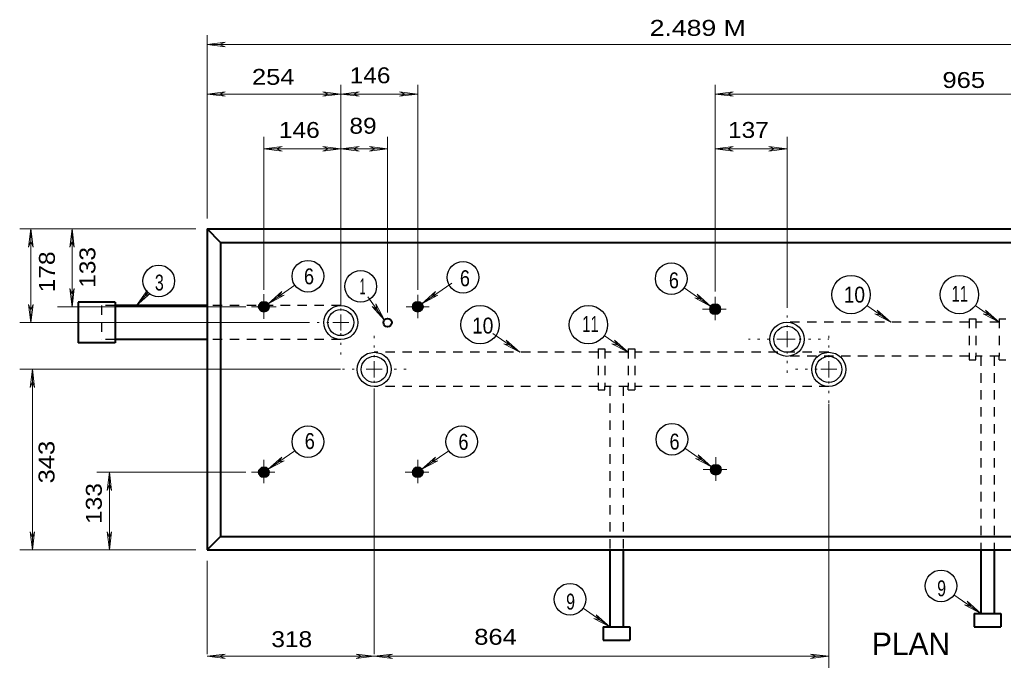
# Model space of a CAD drawing. Extents: x 312583 to 312854, y 144419 to 144597.
# Drawn here: x 312769.06 to 312816.07, y 144549.21 to 144579.91 of the extents above; entities that cross this region are included whole.
import ezdxf
from ezdxf.enums import TextEntityAlignment as Align

# ---------------------------------------------------------------- set-up
doc = ezdxf.new("R2010")
doc.units = 0
doc.header["$LTSCALE"] = 0.3
doc.linetypes.add('DOTTED', pattern=[1.5, 0.3, -1.2])
doc.linetypes.add('SHORT_DASHED', pattern=[2.7, 1.5, -1.2])
doc.layers.add('1', color=7, linetype='Continuous', lineweight=25)
doc.layers.add('2', color=7, linetype='Continuous', lineweight=13)

msp = doc.modelspace()

# ---------------------------------------------------------------- linework, layer by layer
at = {"layer": '1', "lineweight": 40}
for p, q in [((312778.0166, 144569.9153), (312840.6303, 144569.9153)), ((312778.0166, 144569.9153), (312778.0166, 144554.5819)), ((312778.6606, 144569.2713), (312778.0166, 144569.9153)), ((312778.6606, 144569.2713), (312839.994, 144569.2713)), ((312778.6606, 144569.2713), (312778.6606, 144555.2183)), ((312773.616, 144566.4116), (312771.8526, 144566.4116)), ((312771.8526, 144566.4116), (312771.8526, 144564.4643)), ((312773.616, 144566.4116), (312773.616, 144564.4643)), ((312778.0166, 144566.2583), (312773.616, 144566.2583)), ((312778.0166, 144564.6253), (312773.616, 144564.6253)), ((312773.616, 144564.4643), (312771.8526, 144564.4643)), ((312778.0166, 144554.5819), (312778.6606, 144555.2183)), ((312778.6606, 144555.2183), (312839.994, 144555.2183)), ((312778.0166, 144554.5819), (312840.6303, 144554.5819)), ((312797.2676, 144554.5819), (312797.2676, 144550.9019)), ((312797.904, 144554.5819), (312797.904, 144550.9019)), ((312814.993, 144554.5819), (312814.993, 144551.5459)), ((312815.637, 144554.5819), (312815.637, 144551.5459)), ((312814.6786, 144551.5459), (312815.9513, 144551.5459)), ((312814.6786, 144551.5459), (312814.6786, 144550.9019)), ((312815.9513, 144551.5459), (312815.9513, 144550.9019)), ((312796.9456, 144550.9019), (312798.226, 144550.9019)), ((312796.9456, 144550.9019), (312796.9456, 144550.2656)), ((312798.226, 144550.9019), (312798.226, 144550.2656)), ((312814.6786, 144550.9019), (312815.9513, 144550.9019)), ((312796.9456, 144550.2656), (312798.226, 144550.2656))]:
    msp.add_line(p, q, dxfattribs=at)
at = {"layer": '1', "linetype": 'SHORT_DASHED'}
for p, q in [((312772.972, 144566.2583), (312772.972, 144564.6253)), ((312773.616, 144566.2583), (312772.972, 144566.2583)), ((312784.4106, 144566.2583), (312778.0166, 144566.2583)), ((312814.4333, 144565.4533), (312805.7316, 144565.4533)), ((312814.4333, 144565.6143), (312814.4333, 144563.6669)), ((312814.4333, 144565.6143), (312814.7553, 144565.6143)), ((312814.7553, 144565.6143), (312814.7553, 144563.8279)), ((312815.8746, 144565.4533), (312814.7553, 144565.4533)), ((312815.8746, 144565.6143), (312815.8746, 144563.8279)), ((312815.8746, 144565.6143), (312816.189, 144565.6143)), ((312773.616, 144564.6253), (312772.972, 144564.6253)), ((312784.4106, 144564.6253), (312778.0166, 144564.6253)), ((312796.708, 144564.0196), (312786.0053, 144564.0196)), ((312796.708, 144564.1806), (312796.708, 144562.2333)), ((312796.708, 144564.1806), (312797.0223, 144564.1806)), ((312797.0223, 144564.1806), (312797.0223, 144562.3866)), ((312798.1416, 144564.0196), (312797.0223, 144564.0196)), ((312798.1416, 144564.1806), (312798.1416, 144562.3866)), ((312798.1416, 144564.1806), (312798.4636, 144564.1806)), ((312798.4636, 144564.1806), (312798.4636, 144562.2333)), ((312807.725, 144564.0196), (312798.4636, 144564.0196)), ((312814.4333, 144563.8279), (312805.7316, 144563.8279)), ((312814.4333, 144563.6669), (312814.7553, 144563.6669)), ((312814.7553, 144563.6669), (312814.7553, 144563.8279)), ((312815.8746, 144563.8279), (312814.7553, 144563.8279)), ((312814.993, 144563.8279), (312814.993, 144554.5819)), ((312815.637, 144563.8279), (312815.637, 144554.5819)), ((312815.8746, 144563.6669), (312815.8746, 144563.8279)), ((312815.8746, 144563.6669), (312816.189, 144563.6669)), ((312796.708, 144562.3866), (312786.0053, 144562.3866)), ((312796.708, 144562.2333), (312797.0223, 144562.2333)), ((312797.0223, 144562.2333), (312797.0223, 144562.3866)), ((312798.1416, 144562.3866), (312797.0223, 144562.3866)), ((312797.2676, 144562.3866), (312797.2676, 144554.5819)), ((312797.904, 144562.3866), (312797.904, 144554.5819)), ((312798.1416, 144562.2333), (312798.1416, 144562.3866)), ((312798.1416, 144562.2333), (312798.4636, 144562.2333)), ((312807.725, 144562.3866), (312798.4636, 144562.3866))]:
    msp.add_line(p, q, dxfattribs=at)
at = {"layer": '1', "lineweight": 40}
for centre, radius in [((312780.7338, 144566.1982), 0.2396), ((312780.7338, 144566.1982), 0.2156), ((312780.7338, 144566.1982), 0.1941), ((312780.7338, 144566.1982), 0.1747), ((312788.0811, 144566.1982), 0.2396), ((312788.0811, 144566.1982), 0.2156), ((312788.0811, 144566.1982), 0.1941), ((312788.0811, 144566.1982), 0.1747), ((312780.7338, 144566.1982), 0.1572), ((312780.7338, 144566.1982), 0.1415), ((312780.7338, 144566.1982), 0.1273), ((312780.7338, 144566.1982), 0.1146), ((312780.7338, 144566.1982), 0.1031), ((312780.7338, 144566.1982), 0.0928), ((312780.7338, 144566.1982), 0.0835), ((312780.7338, 144566.1982), 0.0752), ((312780.7338, 144566.1982), 0.0677), ((312780.7338, 144566.1982), 0.0609), ((312780.7338, 144566.1982), 0.0548), ((312788.0811, 144566.1982), 0.1572), ((312788.0811, 144566.1982), 0.1415), ((312788.0811, 144566.1982), 0.1273), ((312788.0811, 144566.1982), 0.1146), ((312788.0811, 144566.1982), 0.1031), ((312788.0811, 144566.1982), 0.0928), ((312788.0811, 144566.1982), 0.0835), ((312788.0811, 144566.1982), 0.0752), ((312788.0811, 144566.1982), 0.0677), ((312788.0811, 144566.1982), 0.0609), ((312788.0811, 144566.1982), 0.0548), ((312802.2963, 144566.0787), 0.2396), ((312802.2963, 144566.0787), 0.2156), ((312802.2963, 144566.0787), 0.1941), ((312802.2963, 144566.0787), 0.1747), ((312802.2963, 144566.0787), 0.1572), ((312802.2963, 144566.0787), 0.1415), ((312802.2963, 144566.0787), 0.1273), ((312802.2963, 144566.0787), 0.1146), ((312802.2963, 144566.0787), 0.1031), ((312802.2963, 144566.0787), 0.0928), ((312802.2963, 144566.0787), 0.0835), ((312802.2963, 144566.0787), 0.0752), ((312802.2963, 144566.0787), 0.0677), ((312802.2963, 144566.0787), 0.0609), ((312802.2963, 144566.0787), 0.0548), ((312786.6436, 144565.4399), 0.1996), ((312780.7338, 144558.292), 0.2396), ((312780.7338, 144558.292), 0.2156), ((312780.7338, 144558.292), 0.1941), ((312780.7338, 144558.292), 0.1747), ((312780.7338, 144558.292), 0.1572), ((312780.7338, 144558.292), 0.1415), ((312780.7338, 144558.292), 0.1273), ((312780.7338, 144558.292), 0.1146), ((312780.7338, 144558.292), 0.1031), ((312780.7338, 144558.292), 0.0928), ((312780.7338, 144558.292), 0.0835), ((312780.7338, 144558.292), 0.0752), ((312788.0811, 144558.292), 0.2396), ((312788.0811, 144558.292), 0.2156), ((312788.0811, 144558.292), 0.1941), ((312788.0811, 144558.292), 0.1747), ((312788.0811, 144558.292), 0.1572), ((312788.0811, 144558.292), 0.1415), ((312788.0811, 144558.292), 0.1273), ((312788.0811, 144558.292), 0.1146), ((312788.0811, 144558.292), 0.1031), ((312788.0811, 144558.292), 0.0928), ((312788.0811, 144558.292), 0.0835), ((312788.0811, 144558.292), 0.0752), ((312802.3283, 144558.4121), 0.2396), ((312802.3283, 144558.4121), 0.2156), ((312802.3283, 144558.4121), 0.1941), ((312802.3283, 144558.4121), 0.1747), ((312802.3283, 144558.4121), 0.1572), ((312802.3283, 144558.4121), 0.1415), ((312802.3283, 144558.4121), 0.1273), ((312802.3283, 144558.4121), 0.1146), ((312802.3283, 144558.4121), 0.1031), ((312802.3283, 144558.4121), 0.0928), ((312802.3283, 144558.4121), 0.0835), ((312802.3283, 144558.4121), 0.0752), ((312802.3283, 144558.4121), 0.0677), ((312802.3283, 144558.4121), 0.0609), ((312802.3283, 144558.4121), 0.0548), ((312780.7338, 144558.292), 0.0677), ((312780.7338, 144558.292), 0.0609), ((312780.7338, 144558.292), 0.0548), ((312788.0811, 144558.292), 0.0677), ((312788.0811, 144558.292), 0.0609), ((312788.0811, 144558.292), 0.0548)]:
    msp.add_circle(centre, radius, dxfattribs=at)
at = {"layer": '1'}
for centre, radius in [((312784.4074, 144565.4399), 0.8146), ((312784.4074, 144565.4399), 0.6232), ((312805.7304, 144564.6412), 0.8146), ((312805.7304, 144564.6412), 0.6232), ((312786.0047, 144563.2037), 0.8146), ((312807.7269, 144563.2037), 0.8146), ((312786.0047, 144563.2037), 0.6232), ((312807.7269, 144563.2037), 0.6232)]:
    msp.add_circle(centre, radius, dxfattribs=at)
at = {"layer": '2'}
for p, q in [((312778.0166, 144570.4059), (312778.0166, 144579.1689)), ((312778.0166, 144578.7243), (312778.883, 144578.8316)), ((312778.0166, 144578.7243), (312840.6303, 144578.7243)), ((312778.0166, 144578.7243), (312778.883, 144578.6169)), ((312778.883, 144578.8316), (312778.607, 144578.7243)), ((312778.883, 144578.6169), (312778.607, 144578.7243)), ((312784.4106, 144566.2276), (312784.4106, 144576.7999)), ((312788.083, 144567.0019), (312788.083, 144576.7999)), ((312802.297, 144566.9176), (312802.297, 144576.7999)), ((312778.0166, 144576.3553), (312778.883, 144576.4626)), ((312778.0166, 144576.3553), (312778.883, 144576.2479)), ((312778.883, 144576.4626), (312778.607, 144576.3553)), ((312778.883, 144576.2479), (312778.607, 144576.3553)), ((312783.5443, 144576.4626), (312783.8203, 144576.3553)), ((312784.4106, 144576.3553), (312783.5443, 144576.4626)), ((312783.5443, 144576.2479), (312783.8203, 144576.3553)), ((312784.4106, 144576.3553), (312783.5443, 144576.2479)), ((312784.4106, 144576.3553), (312785.277, 144576.4626)), ((312784.4106, 144576.3553), (312785.277, 144576.2479)), ((312785.277, 144576.4626), (312785.001, 144576.3553)), ((312785.277, 144576.2479), (312785.001, 144576.3553)), ((312787.2166, 144576.4626), (312787.4926, 144576.3553)), ((312788.083, 144576.3553), (312787.2166, 144576.4626)), ((312787.2166, 144576.4626), (312787.4926, 144576.3553)), ((312788.083, 144576.3553), (312787.2166, 144576.4626)), ((312787.2166, 144576.2479), (312787.4926, 144576.3553)), ((312788.083, 144576.3553), (312787.2166, 144576.2479)), ((312787.2166, 144576.2479), (312787.4926, 144576.3553)), ((312788.083, 144576.3553), (312787.2166, 144576.2479)), ((312802.297, 144576.3553), (312803.1633, 144576.4626)), ((312802.297, 144576.3553), (312803.1633, 144576.2479)), ((312826.5773, 144576.3553), (312802.297, 144576.3553)), ((312803.1633, 144576.4626), (312802.8873, 144576.3553)), ((312803.1633, 144576.2479), (312802.8873, 144576.3553)), ((312780.7306, 144567.0019), (312780.7306, 144574.3159)), ((312786.6416, 144565.9209), (312786.6416, 144574.3159)), ((312805.7316, 144566.2199), (312805.7316, 144574.3159)), ((312780.7306, 144573.7409), (312781.597, 144573.8483)), ((312780.7306, 144573.7409), (312781.597, 144573.6336)), ((312781.597, 144573.8483), (312781.321, 144573.7409)), ((312781.597, 144573.6336), (312781.321, 144573.7409)), ((312783.5443, 144573.8483), (312783.8203, 144573.7409)), ((312784.4106, 144573.7409), (312783.5443, 144573.8483)), ((312783.5443, 144573.6336), (312783.8203, 144573.7409)), ((312784.4106, 144573.7409), (312783.5443, 144573.6336)), ((312784.4106, 144573.7409), (312785.277, 144573.8483)), ((312784.4106, 144573.7409), (312785.277, 144573.6336)), ((312785.277, 144573.8483), (312785.001, 144573.7409)), ((312785.277, 144573.6336), (312785.001, 144573.7409)), ((312785.7753, 144573.8483), (312786.0513, 144573.7409)), ((312786.6416, 144573.7409), (312785.7753, 144573.8483)), ((312785.7753, 144573.6336), (312786.0513, 144573.7409)), ((312786.6416, 144573.7409), (312785.7753, 144573.6336)), ((312802.297, 144573.7409), (312803.1633, 144573.8483)), ((312802.297, 144573.7409), (312803.1633, 144573.6336)), ((312802.297, 144573.7409), (312805.7316, 144573.7409)), ((312803.1633, 144573.8483), (312802.8873, 144573.7409)), ((312803.1633, 144573.6336), (312802.8873, 144573.7409)), ((312804.8653, 144573.8483), (312805.1413, 144573.7409)), ((312805.7316, 144573.7409), (312804.8653, 144573.8483)), ((312804.8653, 144573.6336), (312805.1413, 144573.7409)), ((312805.7316, 144573.7409), (312804.8653, 144573.6336)), ((312777.48, 144569.9153), (312769.0593, 144569.9153)), ((312769.5916, 144569.9153), (312769.4843, 144569.0489)), ((312769.5916, 144569.9153), (312769.4843, 144569.0489)), ((312769.5916, 144565.4379), (312769.5916, 144569.9153)), ((312769.5916, 144569.9153), (312769.6989, 144569.0489)), ((312769.5916, 144569.9153), (312769.6989, 144569.0489)), ((312771.5641, 144569.9153), (312771.4568, 144569.0489)), ((312771.5641, 144566.1969), (312771.5641, 144569.9153)), ((312771.5641, 144569.9153), (312771.6714, 144569.0489)), ((312769.4843, 144569.0489), (312769.5916, 144569.3249)), ((312769.4843, 144569.0489), (312769.5916, 144569.3249)), ((312769.6989, 144569.0489), (312769.5916, 144569.3249)), ((312769.6989, 144569.0489), (312769.5916, 144569.3249)), ((312771.4568, 144569.0489), (312771.5641, 144569.3249)), ((312771.6714, 144569.0489), (312771.5641, 144569.3249)), ((312789.7083, 144567.3239), (312788.2746, 144566.3349)), ((312771.4568, 144567.0633), (312771.5641, 144566.7873)), ((312771.5641, 144566.1969), (312771.4568, 144567.0633)), ((312771.6714, 144567.0633), (312771.5641, 144566.7873)), ((312771.5641, 144566.1969), (312771.6714, 144567.0633)), ((312774.6433, 144566.2583), (312775.1493, 144566.9713)), ((312775.203, 144566.8716), (312774.6433, 144566.2583)), ((312775.1493, 144566.9713), (312775.042, 144566.6953)), ((312782.2103, 144567.2243), (312780.93, 144566.3349)), ((312780.93, 144566.3349), (312781.5816, 144566.9176)), ((312781.5816, 144566.9176), (312781.413, 144566.6723)), ((312788.2746, 144566.3349), (312788.9263, 144566.9176)), ((312788.9263, 144566.9176), (312788.7653, 144566.6723)), ((312800.8173, 144567.1016), (312802.0976, 144566.2123)), ((312774.6433, 144566.2583), (312775.3026, 144566.8256)), ((312775.3026, 144566.8256), (312775.042, 144566.6953)), ((312780.7306, 144565.6143), (312780.7306, 144566.8026)), ((312780.93, 144566.3349), (312781.7043, 144566.7413)), ((312781.7043, 144566.7413), (312781.413, 144566.6723)), ((312785.7063, 144566.6723), (312786.4883, 144565.5606)), ((312788.083, 144565.6526), (312788.083, 144566.7566)), ((312788.2746, 144566.3349), (312789.049, 144566.7413)), ((312789.049, 144566.7413), (312788.7653, 144566.6723)), ((312801.3233, 144566.6186), (312801.6146, 144566.5496)), ((312802.0976, 144566.2123), (312801.3233, 144566.6186)), ((312801.446, 144566.7949), (312801.6146, 144566.5496)), ((312802.0976, 144566.2123), (312801.446, 144566.7949)), ((312802.297, 144565.5529), (312802.297, 144566.6723)), ((312769.4843, 144566.3043), (312769.5916, 144566.0283)), ((312769.5916, 144565.4379), (312769.4843, 144566.3043)), ((312769.6989, 144566.3043), (312769.5916, 144566.0283)), ((312769.5916, 144565.4379), (312769.6989, 144566.3043)), ((312779.872, 144566.1969), (312770.8636, 144566.1969)), ((312781.321, 144566.1969), (312780.1326, 144566.1969)), ((312785.9056, 144566.2123), (312786.151, 144566.0436)), ((312786.4883, 144565.5606), (312785.9056, 144566.2123)), ((312786.0743, 144566.3349), (312786.151, 144566.0436)), ((312786.4883, 144565.5606), (312786.0743, 144566.3349)), ((312788.6273, 144566.1969), (312787.5233, 144566.1969)), ((312802.826, 144566.0819), (312801.699, 144566.0819)), ((312809.5496, 144566.2506), (312810.6996, 144565.4533)), ((312810.048, 144566.0359), (312810.209, 144565.7906)), ((312810.6996, 144565.4533), (312810.048, 144566.0359)), ((312814.7246, 144566.2506), (312815.8746, 144565.4533)), ((312815.223, 144566.0359), (312815.3916, 144565.7906)), ((312815.8746, 144565.4533), (312815.223, 144566.0359)), ((312782.839, 144565.4379), (312769.0593, 144565.4379)), ((312784.4106, 144565.4379), (312784.0273, 144565.4379)), ((312784.4106, 144565.4379), (312784.4106, 144565.8213)), ((312784.4106, 144565.4379), (312784.794, 144565.4379)), ((312784.4106, 144565.4379), (312784.4106, 144565.0546)), ((312809.9253, 144565.8596), (312810.209, 144565.7906)), ((312810.6996, 144565.4533), (312809.9253, 144565.8596)), ((312815.1003, 144565.8596), (312815.3916, 144565.7906)), ((312815.8746, 144565.4533), (312815.1003, 144565.8596)), ((312805.7316, 144564.6406), (312805.7316, 144565.0239)), ((312791.671, 144564.9166), (312792.9666, 144564.0196)), ((312792.315, 144564.6023), (312792.4836, 144564.3569)), ((312792.9666, 144564.0196), (312792.315, 144564.6023)), ((312796.9993, 144564.8169), (312798.1416, 144564.0196)), ((312797.49, 144564.6023), (312797.6586, 144564.3569)), ((312798.1416, 144564.0196), (312797.49, 144564.6023)), ((312805.7316, 144564.6406), (312805.3483, 144564.6406)), ((312805.7316, 144564.6406), (312806.115, 144564.6406)), ((312805.7316, 144564.6406), (312805.7316, 144564.2573)), ((312792.1923, 144564.4259), (312792.4836, 144564.3569)), ((312792.9666, 144564.0196), (312792.1923, 144564.4259)), ((312797.3673, 144564.4259), (312797.6586, 144564.3569)), ((312798.1416, 144564.0196), (312797.3673, 144564.4259)), ((312786.0053, 144563.2069), (312786.0053, 144563.5903)), ((312807.725, 144563.2069), (312807.725, 144563.5903)), ((312784.3876, 144563.2069), (312769.0593, 144563.2069)), ((312769.6664, 144563.2069), (312769.5591, 144562.3406)), ((312769.6664, 144563.2069), (312769.7737, 144562.3406)), ((312769.6664, 144554.5819), (312769.6664, 144563.2069)), ((312786.0053, 144563.2069), (312785.622, 144563.2069)), ((312786.0053, 144563.2069), (312786.3886, 144563.2069)), ((312786.0053, 144563.2069), (312786.0053, 144562.8236)), ((312807.725, 144563.2069), (312807.3416, 144563.2069)), ((312807.725, 144563.2069), (312808.1083, 144563.2069)), ((312807.725, 144563.2069), (312807.725, 144562.8236)), ((312769.5591, 144562.3406), (312769.6664, 144562.6166)), ((312769.7737, 144562.3406), (312769.6664, 144562.6166)), ((312786.0053, 144562.2869), (312786.0053, 144549.5986)), ((312807.725, 144561.5586), (312807.725, 144548.9546)), ((312782.2103, 144559.3199), (312780.93, 144558.4306)), ((312789.5626, 144559.3199), (312788.2746, 144558.4306)), ((312800.848, 144559.4349), (312802.1283, 144558.5456)), ((312780.7306, 144557.7636), (312780.7306, 144558.8906)), ((312780.93, 144558.4306), (312781.5816, 144559.0133)), ((312780.93, 144558.4306), (312781.7043, 144558.8369)), ((312781.5816, 144559.0133), (312781.413, 144558.7679)), ((312781.7043, 144558.8369), (312781.413, 144558.7679)), ((312788.083, 144557.7636), (312788.083, 144558.8906)), ((312788.2746, 144558.4306), (312788.9263, 144559.0133)), ((312788.2746, 144558.4306), (312789.049, 144558.8369)), ((312788.9263, 144559.0133), (312788.7653, 144558.7679)), ((312789.049, 144558.8369), (312788.7653, 144558.7679)), ((312801.3616, 144558.9519), (312801.6453, 144558.8829)), ((312802.1283, 144558.5456), (312801.3616, 144558.9519)), ((312801.4843, 144559.1283), (312801.6453, 144558.8829)), ((312802.1283, 144558.5456), (312801.4843, 144559.1283)), ((312802.3276, 144557.8863), (312802.3276, 144559.0056)), ((312802.8566, 144558.4153), (312801.7296, 144558.4153)), ((312779.872, 144558.2926), (312772.742, 144558.2926)), ((312773.3476, 144558.2926), (312773.2403, 144557.4263)), ((312773.3476, 144554.5819), (312773.3476, 144558.2926)), ((312773.3476, 144558.2926), (312773.455, 144557.4263)), ((312781.2596, 144558.2926), (312780.1403, 144558.2926)), ((312788.612, 144558.2926), (312787.485, 144558.2926)), ((312773.2403, 144557.4263), (312773.3476, 144557.7023)), ((312773.455, 144557.4263), (312773.3476, 144557.7023)), ((312769.5591, 144555.4483), (312769.6664, 144555.1723)), ((312769.6664, 144554.5819), (312769.5591, 144555.4483)), ((312769.7737, 144555.4483), (312769.6664, 144555.1723)), ((312769.6664, 144554.5819), (312769.7737, 144555.4483)), ((312773.2403, 144555.4483), (312773.3476, 144555.1723)), ((312773.3476, 144554.5819), (312773.2403, 144555.4483)), ((312773.455, 144555.4483), (312773.3476, 144555.1723)), ((312773.3476, 144554.5819), (312773.455, 144555.4483)), ((312777.48, 144554.5819), (312769.0593, 144554.5819)), ((312778.0166, 144554.0529), (312778.0166, 144549.5986)), ((312813.7126, 144552.4353), (312814.993, 144551.5459)), ((312795.9873, 144551.7913), (312797.2676, 144550.9019)), ((312814.2186, 144551.9523), (312814.51, 144551.8833)), ((312814.993, 144551.5459), (312814.2186, 144551.9523)), ((312814.3413, 144552.1286), (312814.51, 144551.8833)), ((312814.993, 144551.5459), (312814.3413, 144552.1286)), ((312796.616, 144551.4846), (312796.777, 144551.2393)), ((312797.2676, 144550.9019), (312796.616, 144551.4846)), ((312796.4933, 144551.3083), (312796.777, 144551.2393)), ((312797.2676, 144550.9019), (312796.4933, 144551.3083)), ((312778.0166, 144549.4989), (312778.883, 144549.6063)), ((312778.0166, 144549.4989), (312778.883, 144549.3916)), ((312778.883, 144549.6063), (312778.607, 144549.4989)), ((312778.883, 144549.3916), (312778.607, 144549.4989)), ((312785.139, 144549.6063), (312785.415, 144549.4989)), ((312786.0053, 144549.4989), (312785.139, 144549.6063)), ((312785.139, 144549.3916), (312785.415, 144549.4989)), ((312786.0053, 144549.4989), (312785.139, 144549.3916)), ((312786.0053, 144549.4989), (312786.8716, 144549.6063)), ((312786.0053, 144549.4989), (312786.8716, 144549.3916)), ((312786.8716, 144549.6063), (312786.5956, 144549.4989)), ((312786.8716, 144549.3916), (312786.5956, 144549.4989)), ((312806.8586, 144549.6063), (312807.1346, 144549.4989)), ((312807.725, 144549.4989), (312806.8586, 144549.6063)), ((312806.8586, 144549.3916), (312807.1346, 144549.4989)), ((312807.725, 144549.4989), (312806.8586, 144549.3916))]:
    msp.add_line(p, q, dxfattribs=at)
at = {"layer": '2', "linetype": 'DOTTED'}
for p, q in [((312784.4106, 144566.0129), (312784.4106, 144567.0326)), ((312805.7316, 144565.2156), (312805.7316, 144566.2199)), ((312783.8356, 144565.4379), (312782.839, 144565.4379)), ((312784.4106, 144563.9123), (312784.4106, 144565.0546)), ((312786.0053, 144563.7819), (312786.0053, 144564.8093)), ((312805.3483, 144564.6406), (312803.884, 144564.6406)), ((312806.3066, 144564.6406), (312807.7326, 144564.6406)), ((312807.725, 144563.7819), (312807.725, 144564.8859)), ((312805.7316, 144564.0656), (312805.7316, 144562.9769)), ((312785.047, 144563.2069), (312784.3876, 144563.2069)), ((312786.9636, 144563.2069), (312787.6153, 144563.2069)), ((312807.1653, 144563.2069), (312806.0383, 144563.2069)), ((312786.0053, 144561.6429), (312786.0053, 144562.8236)), ((312807.725, 144562.6319), (312807.725, 144561.5586))]:
    msp.add_line(p, q, dxfattribs=at)
at = {"layer": '2'}
for points in [[(312778.0166, 144576.3553), (312784.4106, 144576.3553), (312788.083, 144576.3553)], [(312780.7306, 144573.7409), (312784.4106, 144573.7409), (312786.6416, 144573.7409)], [(312778.0166, 144549.4989), (312786.0053, 144549.4989), (312807.725, 144549.4989)]]:
    msp.add_lwpolyline(points, dxfattribs=at)
at = {"layer": '2', "lineweight": 25}
for centre, radius in [((312782.8326, 144567.6549), 0.7557), ((312790.2478, 144567.5974), 0.7557), ((312800.1976, 144567.5354), 0.7557), ((312775.7083, 144567.4293), 0.7557), ((312785.3613, 144567.1693), 0.7557), ((312808.7938, 144566.7758), 0.9185), ((312813.9707, 144566.7758), 0.9185), ((312791.0647, 144565.3383), 0.9185), ((312796.2416, 144565.3383), 0.9185), ((312782.8326, 144559.7486), 0.7557), ((312790.1798, 144559.7486), 0.7557), ((312800.2295, 144559.8687), 0.7557), ((312813.0923, 144552.864), 0.7557), ((312795.3631, 144552.2251), 0.7557)]:
    msp.add_circle(centre, radius, dxfattribs=at)

# ---------------------------------------------------------------- texts
at = {"layer": '2'}
for s, width, p in [('2.489 M', 1.25, (312799.1706, 144579.1347)), ('146 ', 1.15, (312784.8307, 144576.8692)), ('254 ', 1.2, (312780.1594, 144576.7945)), ('965 ', 1.2, (312813.1621, 144576.6449)), ('146 ', 1.15, (312781.4501, 144574.2595)), ('89 ', 1.15, (312784.8183, 144574.4598)), ('137 ', 1.15, (312802.913, 144574.2596)), ('6', 0.85, (312782.6469, 144567.2675)), ('6', 0.85, (312790.098, 144567.1764)), ('6', 0.85, (312800.0866, 144567.0777)), ('3', 0.75, (312775.5224, 144566.9704)), ('1', 0.5, (312785.3074, 144566.7845)), ('10', 0.9, (312808.4419, 144566.3935)), ('11', 0.7, (312813.5922, 144566.4309)), ('10', 0.9, (312790.6792, 144564.9148)), ('11', 0.7, (312795.9416, 144564.9896)), ('6', 0.85, (312782.6842, 144559.4005)), ('6', 0.85, (312790.0289, 144559.3632)), ('6', 0.85, (312800.1174, 144559.3736)), ('9', 0.75, (312812.9087, 144552.3664)), ('9', 0.75, (312795.1756, 144551.73)), ('318 ', 1.15, (312781.0883, 144549.9381)), ('864 ', 1.2, (312790.7843, 144550.0502))]:
    msp.add_text(s, height=0.76, dxfattribs=dict(at, width=width)).set_placement(p)
for s, width, p in [('178 ', 1.15, (312770.7409, 144566.8864)), ('133 ', 1.15, (312772.6761, 144567.0992)), ('343 ', 1.2, (312770.7222, 144557.7577)), ('133 ', 1.15, (312772.9838, 144555.8225))]:
    msp.add_text(s, height=0.76, rotation=90, dxfattribs=dict(at, width=width)).set_placement(p)
msp.add_text('PLAN', height=1.07, dxfattribs=at).set_placement((312811.6585, 144549.5603), align=Align.CENTER)

doc.saveas('drawing.dxf')
